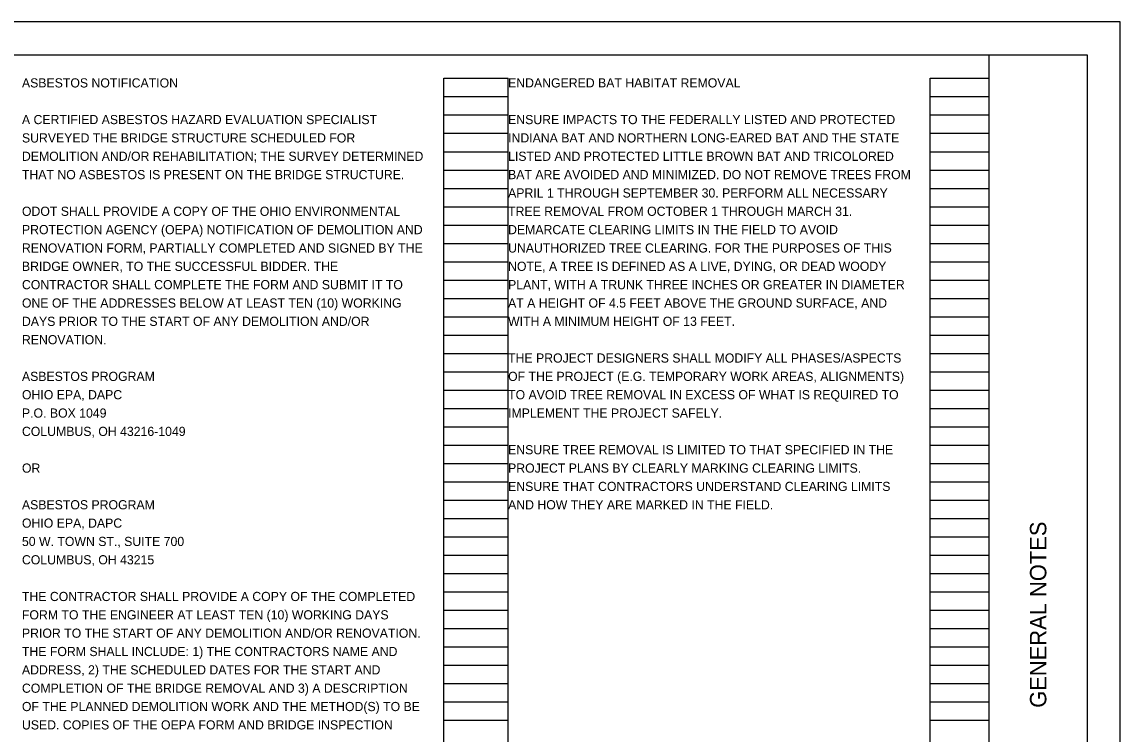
# Model space of a CAD drawing. Extents: x 0 to 34, y 0 to 22.
# Drawn here: x 17.24 to 34, y 11.13 to 22 of the extents above; entities that cross this region are included whole.
import ezdxf

# ---------------------------------------------------------------- set-up
doc = ezdxf.new("R2010")
doc.units = 0
for name, color, linetype in [('SH_Border', 7, 'Continuous'), ('SH_Cut_Line', 7, 'Continuous'), ('SH_Data', 7, 'Continuous'), ('SH_Text', 7, 'Continuous')]:
    doc.layers.add(name, color=color, linetype=linetype)

msp = doc.modelspace()

# ---------------------------------------------------------------- linework, layer by layer
at = {"layer": 'SH_Border'}
msp.add_line((32, 0.5), (32, 21.5), dxfattribs=at)
msp.add_lwpolyline([(1.5, 21.5), (33.5, 21.5), (33.5, 0.5), (1.5, 0.5)], close=True, dxfattribs=at)
at = {"layer": 'SH_Cut_Line'}
msp.add_lwpolyline([(0, 0), (34, 0), (34, 22), (0, 22)], close=True, dxfattribs=at)
at = {"layer": 'SH_Data'}
for p, q in [((23.68, 0.98), (23.68, 21.14)), ((23.68, 21.14), (24.66, 21.14)), ((24.66, 0.98), (24.66, 21.14)), ((31.1, 0.98), (31.1, 21.14)), ((31.1, 21.14), (32, 21.14)), ((32, 0.98), (32, 21.14)), ((23.68, 20.86), (24.66, 20.86)), ((31.1, 20.86), (32, 20.86)), ((23.68, 20.58), (24.66, 20.58)), ((31.1, 20.58), (32, 20.58)), ((23.68, 20.3), (24.66, 20.3)), ((31.1, 20.3), (32, 20.3)), ((23.68, 20.02), (24.66, 20.02)), ((31.1, 20.02), (32, 20.02)), ((23.68, 19.74), (24.66, 19.74)), ((31.1, 19.74), (32, 19.74)), ((23.68, 19.46), (24.66, 19.46)), ((31.1, 19.46), (32, 19.46)), ((23.68, 19.18), (24.66, 19.18)), ((31.1, 19.18), (32, 19.18)), ((23.68, 18.9), (24.66, 18.9)), ((31.1, 18.9), (32, 18.9)), ((23.68, 18.62), (24.66, 18.62)), ((31.1, 18.62), (32, 18.62)), ((23.68, 18.34), (24.66, 18.34)), ((31.1, 18.34), (32, 18.34)), ((23.68, 18.06), (24.66, 18.06)), ((31.1, 18.06), (32, 18.06)), ((23.68, 17.78), (24.66, 17.78)), ((31.1, 17.78), (32, 17.78)), ((23.68, 17.5), (24.66, 17.5)), ((31.1, 17.5), (32, 17.5)), ((23.68, 17.22), (24.66, 17.22)), ((31.1, 17.22), (32, 17.22)), ((23.68, 16.94), (24.66, 16.94)), ((31.1, 16.94), (32, 16.94)), ((23.68, 16.66), (24.66, 16.66)), ((31.1, 16.66), (32, 16.66)), ((23.68, 16.38), (24.66, 16.38)), ((31.1, 16.38), (32, 16.38)), ((23.68, 16.1), (24.66, 16.1)), ((31.1, 16.1), (32, 16.1)), ((23.68, 15.82), (24.66, 15.82)), ((31.1, 15.82), (32, 15.82)), ((23.68, 15.54), (24.66, 15.54)), ((31.1, 15.54), (32, 15.54)), ((23.68, 15.26), (24.66, 15.26)), ((31.1, 15.26), (32, 15.26)), ((23.68, 14.98), (24.66, 14.98)), ((31.1, 14.98), (32, 14.98)), ((23.68, 14.7), (24.66, 14.7)), ((31.1, 14.7), (32, 14.7)), ((23.68, 14.42), (24.66, 14.42)), ((31.1, 14.42), (32, 14.42)), ((23.68, 14.14), (24.66, 14.14)), ((31.1, 14.14), (32, 14.14)), ((23.68, 13.86), (24.66, 13.86)), ((31.1, 13.86), (32, 13.86)), ((23.68, 13.58), (24.66, 13.58)), ((31.1, 13.58), (32, 13.58)), ((23.68, 13.3), (24.66, 13.3)), ((31.1, 13.3), (32, 13.3)), ((23.68, 13.02), (24.66, 13.02)), ((31.1, 13.02), (32, 13.02)), ((23.68, 12.74), (24.66, 12.74)), ((31.1, 12.74), (32, 12.74)), ((23.68, 12.46), (24.66, 12.46)), ((31.1, 12.46), (32, 12.46)), ((23.68, 12.18), (24.66, 12.18)), ((31.1, 12.18), (32, 12.18)), ((23.68, 11.9), (24.66, 11.9)), ((31.1, 11.9), (32, 11.9)), ((23.68, 11.62), (24.66, 11.62)), ((31.1, 11.62), (32, 11.62)), ((23.68, 11.34), (24.66, 11.34)), ((31.1, 11.34), (32, 11.34))]:
    msp.add_line(p, q, dxfattribs=at)

# ---------------------------------------------------------------- texts
msp.add_text('GENERAL NOTES', height=0.25, rotation=90, dxfattribs=at).set_placement((32.875, 11.531))
at = {"layer": 'SH_Text'}
for s, p in [('ASBESTOS NOTIFICATION', (17.24, 21)), ('ENDANGERED BAT HABITAT REMOVAL', (24.66, 21)), ('A CERTIFIED ASBESTOS HAZARD EVALUATION SPECIALIST ', (17.24, 20.44)), ('ENSURE IMPACTS TO THE FEDERALLY LISTED AND PROTECTED ', (24.66, 20.44)), ('SURVEYED THE BRIDGE STRUCTURE SCHEDULED FOR ', (17.24, 20.16)), ('INDIANA BAT AND NORTHERN LONG-EARED BAT AND THE STATE ', (24.66, 20.16)), ('DEMOLITION AND/OR REHABILITATION; THE SURVEY DETERMINED ', (17.24, 19.88)), ('LISTED AND PROTECTED LITTLE BROWN BAT AND TRICOLORED ', (24.66, 19.88)), ('THAT NO ASBESTOS IS PRESENT ON THE BRIDGE STRUCTURE. ', (17.24, 19.6)), ('BAT ARE AVOIDED AND MINIMIZED. DO NOT REMOVE TREES FROM ', (24.66, 19.6)), ('APRIL 1 THROUGH SEPTEMBER 30. PERFORM ALL NECESSARY ', (24.66, 19.32)), ('ODOT SHALL PROVIDE A COPY OF THE OHIO ENVIRONMENTAL ', (17.24, 19.04)), ('TREE REMOVAL FROM OCTOBER 1 THROUGH MARCH 31. ', (24.66, 19.04)), ('PROTECTION AGENCY (OEPA) NOTIFICATION OF DEMOLITION AND ', (17.24, 18.76)), ('DEMARCATE CLEARING LIMITS IN THE FIELD TO AVOID ', (24.66, 18.76)), ('RENOVATION FORM, PARTIALLY COMPLETED AND SIGNED BY THE ', (17.24, 18.48)), ('UNAUTHORIZED TREE CLEARING. FOR THE PURPOSES OF THIS ', (24.66, 18.48)), ('BRIDGE OWNER, TO THE SUCCESSFUL BIDDER. THE ', (17.24, 18.2)), ('NOTE, A TREE IS DEFINED AS A LIVE, DYING, OR DEAD WOODY ', (24.66, 18.2)), ('CONTRACTOR SHALL COMPLETE THE FORM AND SUBMIT IT TO ', (17.24, 17.92)), ('PLANT, WITH A TRUNK THREE INCHES OR GREATER IN DIAMETER ', (24.66, 17.92)), ('ONE OF THE ADDRESSES BELOW AT LEAST TEN (10) WORKING ', (17.24, 17.64)), ('AT A HEIGHT OF 4.5 FEET ABOVE THE GROUND SURFACE, AND ', (24.66, 17.64)), ('DAYS PRIOR TO THE START OF ANY DEMOLITION AND/OR ', (17.24, 17.36)), ('WITH A MINIMUM HEIGHT OF 13 FEET.', (24.66, 17.36)), ('RENOVATION. ', (17.24, 17.08)), ('THE PROJECT DESIGNERS SHALL MODIFY ALL PHASES/ASPECTS ', (24.66, 16.8)), ('ASBESTOS PROGRAM ', (17.24, 16.52)), ('OF THE PROJECT (E.G. TEMPORARY WORK AREAS, ALIGNMENTS) ', (24.66, 16.52)), ('OHIO EPA, DAPC ', (17.24, 16.24)), ('TO AVOID TREE REMOVAL IN EXCESS OF WHAT IS REQUIRED TO ', (24.66, 16.24)), ('P.O. BOX 1049 ', (17.24, 15.96)), ('IMPLEMENT THE PROJECT SAFELY.', (24.66, 15.96)), ('COLUMBUS, OH 43216-1049 ', (17.24, 15.68)), ('ENSURE TREE REMOVAL IS LIMITED TO THAT SPECIFIED IN THE ', (24.66, 15.4)), ('OR ', (17.24, 15.12)), ('PROJECT PLANS BY CLEARLY MARKING CLEARING LIMITS. ', (24.66, 15.12)), ('ENSURE THAT CONTRACTORS UNDERSTAND CLEARING LIMITS ', (24.66, 14.84)), ('ASBESTOS PROGRAM ', (17.24, 14.56)), ('AND HOW THEY ARE MARKED IN THE FIELD.', (24.66, 14.56)), ('OHIO EPA, DAPC ', (17.24, 14.28)), ('50 W. TOWN ST., SUITE 700 ', (17.24, 14)), ('COLUMBUS, OH 43215 ', (17.24, 13.72)), ('THE CONTRACTOR SHALL PROVIDE A COPY OF THE COMPLETED ', (17.24, 13.16)), ('FORM TO THE ENGINEER AT LEAST TEN (10) WORKING DAYS ', (17.24, 12.88)), ('PRIOR TO THE START OF ANY DEMOLITION AND/OR RENOVATION. ', (17.24, 12.6)), ('THE FORM SHALL INCLUDE: 1) THE CONTRACTORS NAME AND ', (17.24, 12.32)), ('ADDRESS, 2) THE SCHEDULED DATES FOR THE START AND ', (17.24, 12.04)), ('COMPLETION OF THE BRIDGE REMOVAL AND 3) A DESCRIPTION ', (17.24, 11.76)), ('OF THE PLANNED DEMOLITION WORK AND THE METHOD(S) TO BE ', (17.24, 11.48)), ('USED. COPIES OF THE OEPA FORM AND BRIDGE INSPECTION ', (17.24, 11.2))]:
    msp.add_text(s, height=0.14, dxfattribs=at).set_placement(p)

doc.saveas('drawing.dxf')
